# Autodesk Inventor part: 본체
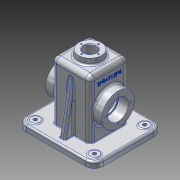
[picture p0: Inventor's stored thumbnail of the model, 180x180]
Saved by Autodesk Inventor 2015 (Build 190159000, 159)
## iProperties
Created: 2016-02
Part Number: 본체
Material: 알루미늄 6061
Document SubType Name: Modeling
Designer: Administrator
Density: 2.7 g/cm^3
Appearance: 알루미늄 - 평지
Mass: 847.465 g
Surface Area: 909.501 cm^2
Volume: 313.876 cm^3
Author: Administrator
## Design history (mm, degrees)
sketch "스케치1"
  geometry: L1 (65, 57.5)-(-65, 57.5); L2 (-65, 57.5)-(-65, -57.5); L3 (-65, -57.5)-(65, -57.5); L4 (65, -57.5)-(65, 57.5); L5 (65, 57.5)-(-65, -57.5); L6 (-65, 57.5)-(65, -57.5); 1 further point
  constraints: 12 end point, 2 midpoint, 2 parallel, 1 horizontal, 1 perpendicular
  dimensions: "d1" = 115 distance between parallel lines of L1 L3; "d2" = 130 distance between parallel lines of L2 L4
extrude "돌출1" new body sketch "스케치1" distance "d3" = 10; taper "d4" = 0 deg
sketch "스케치2"
  geometry: L1 (-60, -52.5)-(60, -52.5); L2 (60, -52.5)-(60, 52.5); L3 (60, 52.5)-(-60, 52.5); L4 (-60, 52.5)-(-60, -52.5); L5 (-60, -52.5)-(60, 52.5); L6 (60, -52.5)-(-60, 52.5); 1 further point
  constraints: 12 end point, 2 midpoint, 2 parallel, 1 horizontal, 1 perpendicular
  dimensions: "d5" = 105 distance between parallel lines of L1 L3; "d6" = 120 distance between parallel lines of L4 L2
extrude "돌출2" join sketch "스케치2" distance "d7" = 2; taper "d8" = 0 deg
sketch "스케치3"
  geometry: L1 (-32.5, -32.5)-(32.5, -32.5); L2 (32.5, -32.5)-(32.5, 32.5); L3 (32.5, 32.5)-(-32.5, 32.5); L4 (-32.5, 32.5)-(-32.5, -32.5); L5 (-32.5, -32.5)-(32.5, 32.5); L6 (32.5, -32.5)-(-32.5, 32.5); 1 further point
  constraints: 12 end point, 2 midpoint, 2 parallel, 1 horizontal, 1 perpendicular
  dimensions: "d9" = 65 distance between parallel lines of L2 L4; "d10" = 65 distance between parallel lines of L1 L3
extrude "돌출3" join sketch "스케치3" distance "d11" = 98; taper "d12" = 0 deg
sketch "스케치4"
  geometry: C1 r 20 at (0, 0); 1 further point
  constraints: 1 centre point, 1 coincident
  dimensions: "d13" = 40 diameter of C1
extrude "돌출4" join sketch "스케치4" distance "d14" = 10; taper "d15" = 0 deg
node "작업 평면1"
sketch "스케치8"
  geometry: L1 (-40.195, 43)-(110.128, 43); L2 (85, -12)-(-20, -12) reference; L3 (32.5, 0)-(32.5, 137.472); L4 (-25, 0)-(90, 0) reference; C1 r 27.5 at (32.5, 43); 1 further point
  constraints: 4 end point, 2 point on line, 1 centre point, 1 horizontal, 1 midpoint, 1 vertical
  dimensions: "d23" = 55 distance between parallel lines of L2 L1; "d24" = 55 diameter of C1
extrude "돌출6" join sketch "스케치8" distance "d25" = 95; taper "d26" = 0 deg
sketch "스케치6"
  geometry: L1 (-27.5, -27.5)-(27.5, -27.5); L2 (27.5, -27.5)-(27.5, 27.5); L3 (27.5, 27.5)-(-27.5, 27.5); L4 (-27.5, 27.5)-(-27.5, -27.5); L5 (-27.5, -27.5)-(27.5, 27.5); L6 (27.5, -27.5)-(-27.5, 27.5); 1 further point
  constraints: 12 end point, 2 midpoint, 2 parallel, 1 horizontal, 1 perpendicular
  dimensions: "d16" = 55 distance between parallel lines of L1 L3; "d17" = 55 distance between parallel lines of L4 L2
extrude "돌출5" cut sketch "스케치6" distance "d18" = 105; taper "d19" = 0 deg
node "작업 평면2"
sketch "스케치10"
  geometry: L1 (32.5, -32.5)-(-32.5, -32.5) reference; L2 (5, -32.5)-(-5, -32.5); L3 (-5, -32.5)-(-5, -47.5); L4 (-5, -47.5)-(5, -47.5); L5 (5, -47.5)-(5, -32.5); L6 (-65, -57.5)-(65, -57.5) reference; L7 (0, -63.602)-(0, 89.117); 1 further point
  constraints: 10 end point, 2 parallel, 2 point on line, 1 horizontal, 1 perpendicular, 1 vertical, 1 other
  dimensions: "d28" = 10 distance between parallel lines of L6 L4; "d29" = 10 distance between parallel lines of L5 L3
extrude "돌출7" join sketch "스케치10" stored distance "d30" = 95; taper "d31" = 0 deg
feature "면 기울기1" dims angle "d32" = 10 deg
sketch "스케치11"
  geometry: C1 r 10.5 at (0, 0); 1 further point
  constraints: 1 centre point, 1 coincident
  dimensions: "d33" = 21 diameter of C1
extrude "돌출8" cut sketch "스케치11" stored distance "d34" = 95; taper "d35" = 0 deg
fillet "모깎기1" dims "d36" = 3
sketch "스케치12"
  geometry: C1 r 27.5 at (0, 0) reference; C2 r 15 at (0, 0); 1 further point
  constraints: 1 centre point, 1 coincident
  dimensions: "d37" = 30 diameter of C2
extrude "돌출9" cut sketch "스케치12" stored distance "d38" = 95; taper "d39" = 0 deg
sketch "스케치13"
  geometry: C1 r 27.5 at (0, 0) reference; C2 r 17.5 at (0, 0); 1 further point
  constraints: 1 centre point, 1 coincident
  dimensions: "d40" = 35 diameter of C2
extrude "돌출10" cut sketch "스케치13" distance "d41" = 17; taper "d42" = 0 deg
fillet "모깎기2" dims "d43" = 15
sketch "스케치14"
  geometry: C1 r 7.5 at (-50, -42.5); C2 r 7.5 at (-50, 42.5); C3 r 7.5 at (50, 42.5); C4 r 7.5 at (50, -42.5); A1 r 15 centre (-50, 42.5) between (-50, 57.5) and (-65, 42.5) reference; A2 r 15 centre (-50, -42.5) between (-65, -42.5) and (-50, -57.5) reference; A3 r 15 centre (50, -42.5) between (50, -57.5) and (65, -42.5) reference; A4 r 15 centre (50, 42.5) between (65, 42.5) and (50, 57.5) reference; 1 further point
  constraints: 4 centre point, 4 coincident, 3 equal radius
  dimensions: "d44" = 15 diameter of C1
extrude "돌출11" join sketch "스케치14" distance "d45" = 1; taper "d46" = 0 deg
fillet "모깎기3" dims "d47" = 10
sketch "스케치15"
  geometry: A1 r 15 centre (100, -85) between (100, -100) and (115, -85) reference; A2 r 15 centre (0, -85) between (-15, -85) and (0, -100) reference; A3 r 15 centre (0, 0) between (0, 15) and (-15, 0) reference; A4 r 15 centre (100, 0) between (115, 0) and (100, 15) reference; 1 further point
hole "구멍1" sketch "스케치15" at (0, 0), (100, 0), (100, -85), (0, -85) diameter "d48" = 6; stored, may be unused: countersink angle "d52" = 90 deg, drill point angle "d54" = 118 deg; dims "d49" = 6, "d50" = 4, "d51" = 2, "d53" = 8
fillet "모깎기4" dims "d55" = 3
fillet "모깎기5" dims "d56" = 8
fillet "모깎기6" dims "d57" = 8
feature "면 기울기2" dims angle "d58" = 5 deg
fillet "모깎기7" dims "d59" = 3
fillet "모깎기8" dims "d60" = 3
fillet "모깎기9" dims "d61" = 3
fillet "모깎기10" dims "d62" = 1
sketch "스케치16"
  geometry: 2 further points
  constraints: 1 vertical alignment
  dimensions: "d63" = 14.5 distance of point (0, 0) point (0, 14.5)
hole "구멍2" sketch "스케치16" at (0, 14.5) diameter "d64" = 2.459; stored, may be unused: countersink angle "d68" = 90 deg, drill point angle "d70" = 118 deg; dims "d65" = 7, "d66" = 4, "d67" = 2, "d69" = 9
sketch "스케치17"
  geometry: C1 r 17.5 at (0, 0) reference; 2 further points
  constraints: 1 vertical alignment
  dimensions: "d74" = 21 distance of C1.centre point (0, 21)
hole "구멍3" sketch "스케치17" at (0, 21) diameter "d75" = 3.242; stored, may be unused: countersink angle "d79" = 90 deg, drill point angle "d81" = 118 deg; dims "d76" = 8, "d77" = 4, "d78" = 2, "d80" = 10
fillet "모깎기11" dims "d85" = 0.3
chamfer "모따기1" distance "d86" = 1; stored, may be unused: second distance "d87" = 2, angle "d88" = 45 deg
sketch "스케치18"
  geometry: L1 (43.625, 18)-(5.375, 18) reference; L2 (-8, 0)-(-8, -89) reference; 2 further points
  constraints: 1 other
  dimensions: "d89" = 26 distance from line of L1 point (24.5, -8); "d90" = 32.5 distance from line of L2 point (24.5, -8)
feature "엠보싱1" sketch "스케치18" dims "d9" = 65, "d10" = 65, "d91" = 0.5, "d92" = 0
node "솔리드1"
mirror "대칭1"
mirror "대칭2"
pattern_circular "원형 패턴1" dims angle "d72" = 360 deg
pattern_circular "원형 패턴2" dims angle "d83" = 360 deg
mirror "대칭3"
other parameters: "d22" = 15, "d27" = -15
